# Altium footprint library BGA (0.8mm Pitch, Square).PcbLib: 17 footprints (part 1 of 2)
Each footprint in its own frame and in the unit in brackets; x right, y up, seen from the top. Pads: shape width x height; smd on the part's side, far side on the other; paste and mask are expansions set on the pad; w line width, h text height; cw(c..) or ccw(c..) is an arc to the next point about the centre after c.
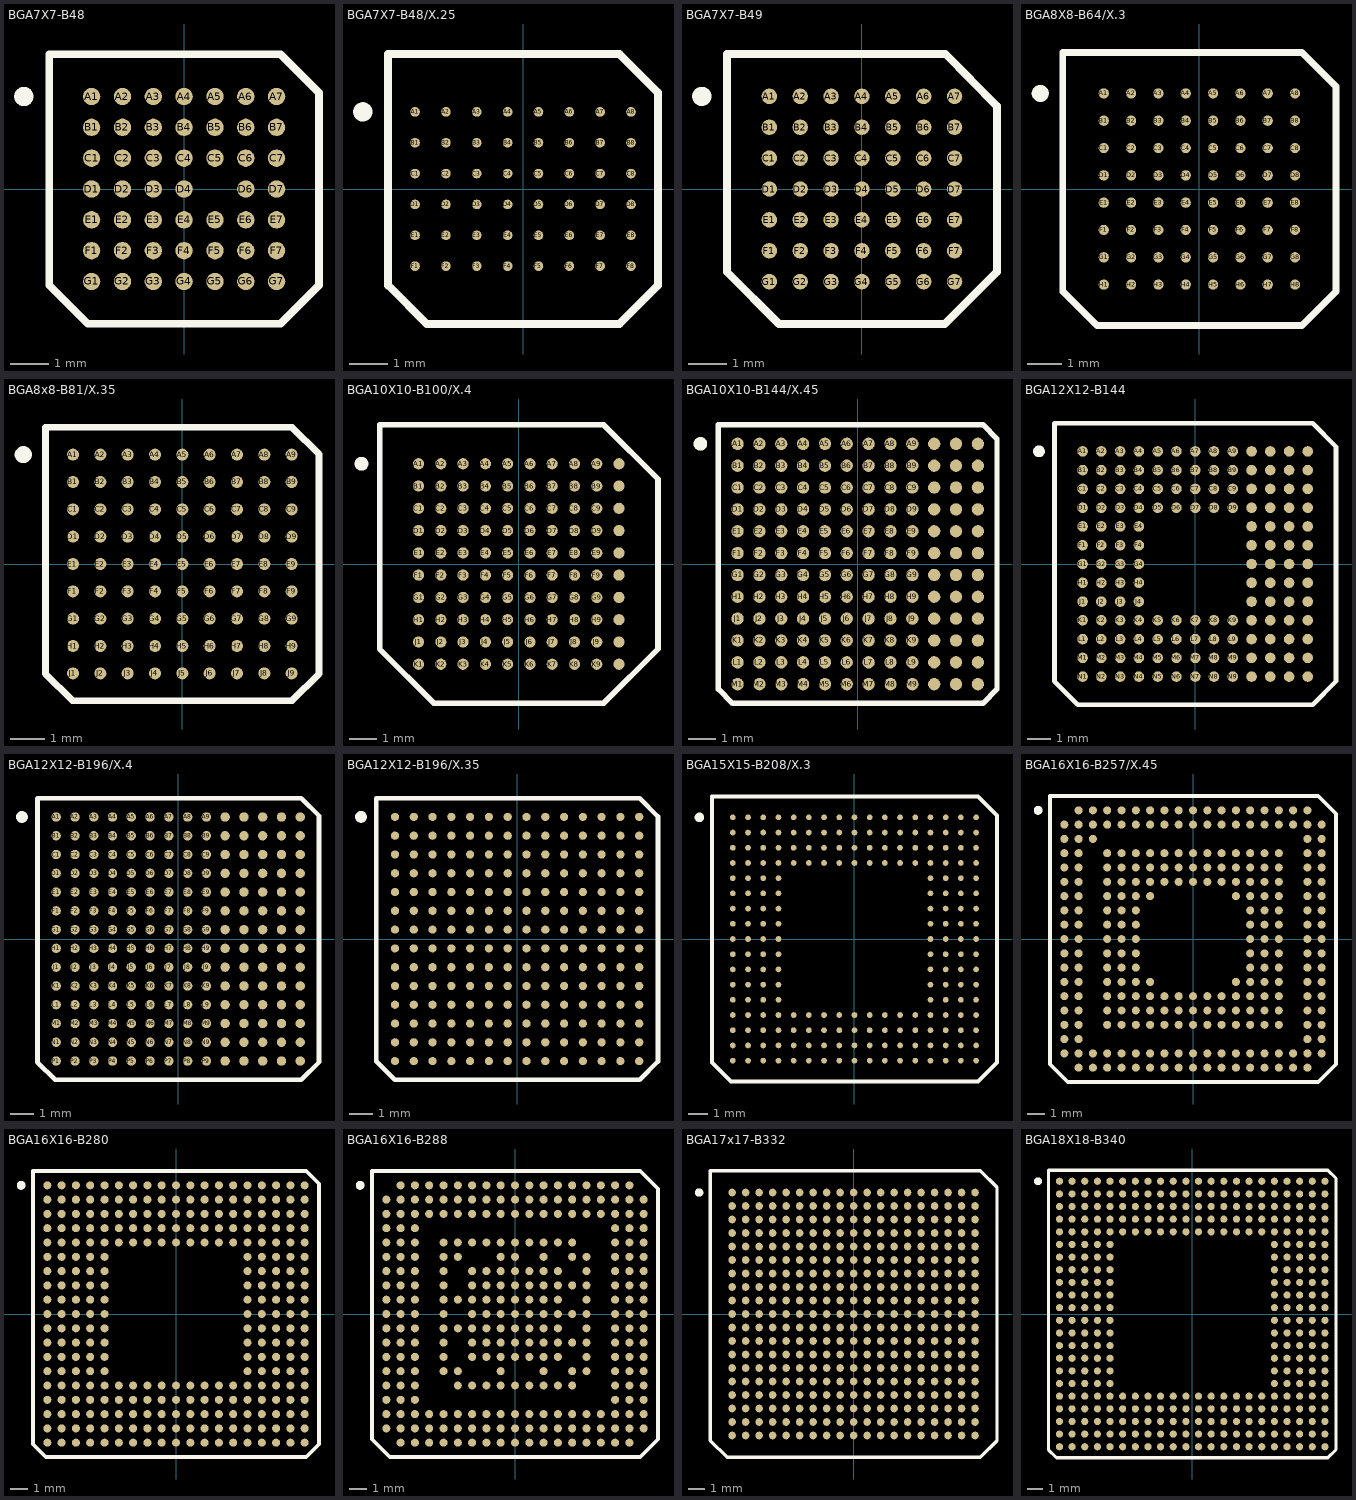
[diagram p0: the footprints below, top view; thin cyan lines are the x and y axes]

## BGA7X7-B48 [mm]
pads (48):
  round 0.45 smd: A1(-2.4,2.4) A2(-1.6,2.4) A3(-0.8,2.4) A4(0,2.4) A5(0.8,2.4) A6(1.6,2.4) A7(2.4,2.4) B1(-2.4,1.6) B2(-1.6,1.6) B3(-0.8,1.6) B4(0,1.6) B5(0.8,1.6) B6(1.6,1.6) B7(2.4,1.6) C1(-2.4,0.8) C2(-1.6,0.8) C3(-0.8,0.8) C4(0,0.8) C5(0.8,0.8) C6(1.6,0.8) C7(2.4,0.8) D1(-2.4,0) D2(-1.6,0) D3(-0.8,0) D4(0,0) D6(1.6,0) D7(2.4,0) E1(-2.4,-0.8) E2(-1.6,-0.8) E3(-0.8,-0.8) E4(0,-0.8) E5(0.8,-0.8) E6(1.6,-0.8) E7(2.4,-0.8) F1(-2.4,-1.6) F2(-1.6,-1.6) F3(-0.8,-1.6) F4(0,-1.6) F5(0.8,-1.6) F6(1.6,-1.6) F7(2.4,-1.6) G1(-2.4,-2.4) G2(-1.6,-2.4) G3(-0.8,-2.4) G4(0,-2.4) G5(0.8,-2.4) G6(1.6,-2.4) G7(2.4,-2.4)
Top Overlay:
  circle w0.25: c-4.16,2.4 r0.125
  lines w0.2: -3.5,-2.5 -3.5,3.5 2.5,3.5 3.5,2.5 3.5,-2.5 2.5,-3.5 -2.5,-3.5 -3.5,-2.5

## BGA7X7-B48/X.25 [mm]
pads (48):
  round 0.25 smd: A1(-2.8,2) A2(-2,2) A3(-1.2,2) A4(-0.4,2) A5(0.4,2) A6(1.2,2) A7(2,2) A8(2.8,2) B1(-2.8,1.2) B2(-2,1.2) B3(-1.2,1.2) B4(-0.4,1.2) B5(0.4,1.2) B6(1.2,1.2) B7(2,1.2) B8(2.8,1.2) C1(-2.8,0.4) C2(-2,0.4) C3(-1.2,0.4) C4(-0.4,0.4) C5(0.4,0.4) C6(1.2,0.4) C7(2,0.4) C8(2.8,0.4) D1(-2.8,-0.4) D2(-2,-0.4) D3(-1.2,-0.4) D4(-0.4,-0.4) D5(0.4,-0.4) D6(1.2,-0.4) D7(2,-0.4) D8(2.8,-0.4) E1(-2.8,-1.2) E2(-2,-1.2) E3(-1.2,-1.2) E4(-0.4,-1.2) E5(0.4,-1.2) E6(1.2,-1.2) E7(2,-1.2) E8(2.8,-1.2) F1(-2.8,-2) F2(-2,-2) F3(-1.2,-2) F4(-0.4,-2) F5(0.4,-2) F6(1.2,-2) F7(2,-2) F8(2.8,-2)
Top Overlay:
  circle w0.25: c-4.155,2 r0.125
  lines w0.2: -3.5,-2.5 -3.5,3.5 2.5,3.5 3.5,2.5 3.5,-2.5 2.5,-3.5 -2.5,-3.5 -3.5,-2.5

## BGA7X7-B49 [mm]
pads (49):
  round 0.4 smd: A1(-2.4,2.4) A2(-1.6,2.4) A3(-0.8,2.4) A4(0,2.4) A5(0.8,2.4) A6(1.6,2.4) A7(2.4,2.4) B1(-2.4,1.6) B2(-1.6,1.6) B3(-0.8,1.6) B4(0,1.6) B5(0.8,1.6) B6(1.6,1.6) B7(2.4,1.6) C1(-2.4,0.8) C2(-1.6,0.8) C3(-0.8,0.8) C4(0,0.8) C5(0.8,0.8) C6(1.6,0.8) C7(2.4,0.8) D1(-2.4,0) D2(-1.6,0) D3(-0.8,0) D4(0,0) D5(0.8,0) D6(1.6,0) D7(2.4,0) E1(-2.4,-0.8) E2(-1.6,-0.8) E3(-0.8,-0.8) E4(0,-0.8) E5(0.8,-0.8) E6(1.6,-0.8) E7(2.4,-0.8) F1(-2.4,-1.6) F2(-1.6,-1.6) F3(-0.8,-1.6) F4(0,-1.6) F5(0.8,-1.6) F6(1.6,-1.6) F7(2.4,-1.6) G1(-2.4,-2.4) G2(-1.6,-2.4) G3(-0.8,-2.4) G4(0,-2.4) G5(0.8,-2.4) G6(1.6,-2.4) G7(2.4,-2.4)
Top Overlay:
  circle w0.25: c-4.15,2.4 r0.125
  lines w0.2: 2.149,3.5 -3.5,3.5 -3.5,-2.149 -2.149,-3.5 2.149,-3.5 3.5,-2.149 3.5,2.149 2.159,3.5

## BGA8X8-B64/X.3 [mm]
pads (64):
  round 0.3 smd: A1(-2.8,2.8) A2(-2,2.8) A3(-1.2,2.8) A4(-0.4,2.8) A5(0.4,2.8) A6(1.2,2.8) A7(2,2.8) A8(2.8,2.8) B1(-2.8,2) B2(-2,2) B3(-1.2,2) B4(-0.4,2) B5(0.4,2) B6(1.2,2) B7(2,2) B8(2.8,2) C1(-2.8,1.2) C2(-2,1.2) C3(-1.2,1.2) C4(-0.4,1.2) C5(0.4,1.2) C6(1.2,1.2) C7(2,1.2) C8(2.8,1.2) D1(-2.8,0.4) D2(-2,0.4) D3(-1.2,0.4) D4(-0.4,0.4) D5(0.4,0.4) D6(1.2,0.4) D7(2,0.4) D8(2.8,0.4) E1(-2.8,-0.4) E2(-2,-0.4) E3(-1.2,-0.4) E4(-0.4,-0.4) E5(0.4,-0.4) E6(1.2,-0.4) E7(2,-0.4) E8(2.8,-0.4) F1(-2.8,-1.2) F2(-2,-1.2) F3(-1.2,-1.2) F4(-0.4,-1.2) F5(0.4,-1.2) F6(1.2,-1.2) F7(2,-1.2) F8(2.8,-1.2) G1(-2.8,-2) G2(-2,-2) G3(-1.2,-2) G4(-0.4,-2) G5(0.4,-2) G6(1.2,-2) G7(2,-2) G8(2.8,-2) H1(-2.8,-2.8) H2(-2,-2.8) H3(-1.2,-2.8) H4(-0.4,-2.8) H5(0.4,-2.8) H6(1.2,-2.8) H7(2,-2.8) H8(2.8,-2.8)
Top Overlay:
  circle w0.25: c-4.66,2.8 r0.125
  lines w0.2: -4,-3 -3,-4 3,-4 4,-3 4,3 3,4 -4,4 -4,-3

## BGA8x8-B81/X.35 [mm]
pads (81):
  round 0.35 smd: A1(-3.2,3.2) A2(-2.4,3.2) A3(-1.6,3.2) A4(-0.8,3.2) A5(0,3.2) A6(0.8,3.2) A7(1.6,3.2) A8(2.4,3.2) A9(3.2,3.2) B1(-3.2,2.4) B2(-2.4,2.4) B3(-1.6,2.4) B4(-0.8,2.4) B5(0,2.4) B6(0.8,2.4) B7(1.6,2.4) B8(2.4,2.4) B9(3.2,2.4) C1(-3.2,1.6) C2(-2.4,1.6) C3(-1.6,1.6) C4(-0.8,1.6) C5(0,1.6) C6(0.8,1.6) C7(1.6,1.6) C8(2.4,1.6) C9(3.2,1.6) D1(-3.2,0.8) D2(-2.4,0.8) D3(-1.6,0.8) D4(-0.8,0.8) D5(0,0.8) D6(0.8,0.8) D7(1.6,0.8) D8(2.4,0.8) D9(3.2,0.8) E1(-3.2,0) E2(-2.4,0) E3(-1.6,0) E4(-0.8,0) E5(0,0) E6(0.8,0) E7(1.6,0) E8(2.4,0) E9(3.2,0) F1(-3.2,-0.8) F2(-2.4,-0.8) F3(-1.6,-0.8) F4(-0.8,-0.8) F5(0,-0.8) F6(0.8,-0.8) F7(1.6,-0.8) F8(2.4,-0.8) F9(3.2,-0.8) G1(-3.2,-1.6) G2(-2.4,-1.6) G3(-1.6,-1.6) G4(-0.8,-1.6) G5(0,-1.6) G6(0.8,-1.6) G7(1.6,-1.6) G8(2.4,-1.6) G9(3.2,-1.6) H1(-3.2,-2.4) H2(-2.4,-2.4) H3(-1.6,-2.4) H4(-0.8,-2.4) H5(0,-2.4) H6(0.8,-2.4) H7(1.6,-2.4) H8(2.4,-2.4) H9(3.2,-2.4) J1(-3.2,-3.2) J2(-2.4,-3.2) J3(-1.6,-3.2) J4(-0.8,-3.2) J5(0,-3.2) J6(0.8,-3.2) J7(1.6,-3.2) J8(2.4,-3.2) J9(3.2,-3.2)
Top Overlay:
  circle w0.25: c-4.655,3.2 r0.125
  lines w0.2: -4,-3.213 -4,4 3.213,4 4,3.213 4,-3.213 3.213,-4 -3.213,-4 -4,-3.213

## BGA10X10-B100/X.4 [mm]
pads (100):
  round 0.4 smd: A1(-3.6,3.6) A2(-2.8,3.6) A3(-2,3.6) A4(-1.2,3.6) A5(-0.4,3.6) A6(0.4,3.6) A7(1.2,3.6) A8(2,3.6) A9(2.8,3.6) A10(3.6,3.6) B1(-3.6,2.8) B2(-2.8,2.8) B3(-2,2.8) B4(-1.2,2.8) B5(-0.4,2.8) B6(0.4,2.8) B7(1.2,2.8) B8(2,2.8) B9(2.8,2.8) B10(3.6,2.8) C1(-3.6,2) C2(-2.8,2) C3(-2,2) C4(-1.2,2) C5(-0.4,2) C6(0.4,2) C7(1.2,2) C8(2,2) C9(2.8,2) C10(3.6,2) D1(-3.6,1.2) D2(-2.8,1.2) D3(-2,1.2) D4(-1.2,1.2) D5(-0.4,1.2) D6(0.4,1.2) D7(1.2,1.2) D8(2,1.2) D9(2.8,1.2) D10(3.6,1.2) E1(-3.6,0.4) E2(-2.8,0.4) E3(-2,0.4) E4(-1.2,0.4) E5(-0.4,0.4) E6(0.4,0.4) E7(1.2,0.4) E8(2,0.4) E9(2.8,0.4) E10(3.6,0.4) F1(-3.6,-0.4) F2(-2.8,-0.4) F3(-2,-0.4) F4(-1.2,-0.4) F5(-0.4,-0.4) F6(0.4,-0.4) F7(1.2,-0.4) F8(2,-0.4) F9(2.8,-0.4) F10(3.6,-0.4) G1(-3.6,-1.2) G2(-2.8,-1.2) G3(-2,-1.2) G4(-1.2,-1.2) G5(-0.4,-1.2) G6(0.4,-1.2) G7(1.2,-1.2) G8(2,-1.2) G9(2.8,-1.2) G10(3.6,-1.2) H1(-3.6,-2) H2(-2.8,-2) H3(-2,-2) H4(-1.2,-2) H5(-0.4,-2) H6(0.4,-2) H7(1.2,-2) H8(2,-2) H9(2.8,-2) H10(3.6,-2) J1(-3.6,-2.8) J2(-2.8,-2.8) J3(-2,-2.8) J4(-1.2,-2.8) J5(-0.4,-2.8) J6(0.4,-2.8) J7(1.2,-2.8) J8(2,-2.8) J9(2.8,-2.8) J10(3.6,-2.8) K1(-3.6,-3.6) K2(-2.8,-3.6) K3(-2,-3.6) K4(-1.2,-3.6) K5(-0.4,-3.6) K6(0.4,-3.6) K7(1.2,-3.6) K8(2,-3.6) K9(2.8,-3.6) K10(3.6,-3.6)
Top Overlay:
  circle w0.25: c-5.65,3.6 r0.125
  lines w0.2: -5,-3.049 -5,5 3.049,5 5,3.049 5,-3.049 3.049,-5 -3.049,-5 -5,-3.049

## BGA10X10-B144/X.45 [mm]
pads (144):
  round 0.45 smd: A1(-4.4,4.4) A2(-3.6,4.4) A3(-2.8,4.4) A4(-2,4.4) A5(-1.2,4.4) A6(-0.4,4.4) A7(0.4,4.4) A8(1.2,4.4) A9(2,4.4) A10(2.8,4.4) A11(3.6,4.4) A12(4.4,4.4) B1(-4.4,3.6) B2(-3.6,3.6) B3(-2.8,3.6) B4(-2,3.6) B5(-1.2,3.6) B6(-0.4,3.6) B7(0.4,3.6) B8(1.2,3.6) B9(2,3.6) B10(2.8,3.6) B11(3.6,3.6) B12(4.4,3.6) C1(-4.4,2.8) C2(-3.6,2.8) C3(-2.8,2.8) C4(-2,2.8) C5(-1.2,2.8) C6(-0.4,2.8) C7(0.4,2.8) C8(1.2,2.8) C9(2,2.8) C10(2.8,2.8) C11(3.6,2.8) C12(4.4,2.8) D1(-4.4,2) D2(-3.6,2) D3(-2.8,2) D4(-2,2) D5(-1.2,2) D6(-0.4,2) D7(0.4,2) D8(1.2,2) D9(2,2) D10(2.8,2) D11(3.6,2) D12(4.4,2) E1(-4.4,1.2) E2(-3.6,1.2) E3(-2.8,1.2) E4(-2,1.2) E5(-1.2,1.2) E6(-0.4,1.2) E7(0.4,1.2) E8(1.2,1.2) E9(2,1.2) E10(2.8,1.2) E11(3.6,1.2) E12(4.4,1.2) F1(-4.4,0.4) F2(-3.6,0.4) F3(-2.8,0.4) F4(-2,0.4) F5(-1.2,0.4) F6(-0.4,0.4) F7(0.4,0.4) F8(1.2,0.4) F9(2,0.4) F10(2.8,0.4) F11(3.6,0.4) F12(4.4,0.4) G1(-4.4,-0.4) G2(-3.6,-0.4) G3(-2.8,-0.4) G4(-2,-0.4) G5(-1.2,-0.4) G6(-0.4,-0.4) G7(0.4,-0.4) G8(1.2,-0.4) G9(2,-0.4) G10(2.8,-0.4) G11(3.6,-0.4) G12(4.4,-0.4) H1(-4.4,-1.2) H2(-3.6,-1.2) H3(-2.8,-1.2) H4(-2,-1.2) H5(-1.2,-1.2) H6(-0.4,-1.2) H7(0.4,-1.2) H8(1.2,-1.2) H9(2,-1.2) H10(2.8,-1.2) H11(3.6,-1.2) H12(4.4,-1.2) J1(-4.4,-2) J2(-3.6,-2) J3(-2.8,-2) J4(-2,-2) J5(-1.2,-2) J6(-0.4,-2) J7(0.4,-2) J8(1.2,-2) J9(2,-2) J10(2.8,-2) J11(3.6,-2) J12(4.4,-2) K1(-4.4,-2.8) K2(-3.6,-2.8) K3(-2.8,-2.8) K4(-2,-2.8) K5(-1.2,-2.8) K6(-0.4,-2.8) K7(0.4,-2.8) K8(1.2,-2.8) K9(2,-2.8) K10(2.8,-2.8) K11(3.6,-2.8) K12(4.4,-2.8) L1(-4.4,-3.6) L2(-3.6,-3.6) L3(-2.8,-3.6) L4(-2,-3.6) L5(-1.2,-3.6) L6(-0.4,-3.6) L7(0.4,-3.6) L8(1.2,-3.6) L9(2,-3.6) L10(2.8,-3.6) L11(3.6,-3.6) L12(4.4,-3.6) M1(-4.4,-4.4) M2(-3.6,-4.4) M3(-2.8,-4.4) M4(-2,-4.4) M5(-1.2,-4.4) M6(-0.4,-4.4) M7(0.4,-4.4) M8(1.2,-4.4) M9(2,-4.4) M10(2.8,-4.4) M11(3.6,-4.4) M12(4.4,-4.4)
Top Overlay:
  circle w0.25: c-5.76,4.4 r0.125
  lines w0.2: -5.1,-4.584 -5.1,5.1 4.584,5.1 5.1,4.584 5.1,-4.584 4.584,-5.1 -4.584,-5.1 -5.1,-4.584

## BGA12X12-B144 [mm]
pads (144):
  round 0.45 smd: A1(-4.8,4.8) A2(-4,4.8) A3(-3.2,4.8) A4(-2.4,4.8) A5(-1.6,4.8) A6(-0.8,4.8) A7(0,4.8) A8(0.8,4.8) A9(1.6,4.8) A10(2.4,4.8) A11(3.2,4.8) A12(4,4.8) A13(4.8,4.8) B1(-4.8,4) B2(-4,4) B3(-3.2,4) B4(-2.4,4) B5(-1.6,4) B6(-0.8,4) B7(0,4) B8(0.8,4) B9(1.6,4) B10(2.4,4) B11(3.2,4) B12(4,4) B13(4.8,4) C1(-4.8,3.2) C2(-4,3.2) C3(-3.2,3.2) C4(-2.4,3.2) C5(-1.6,3.2) C6(-0.8,3.2) C7(0,3.2) C8(0.8,3.2) C9(1.6,3.2) C10(2.4,3.2) C11(3.2,3.2) C12(4,3.2) C13(4.8,3.2) D1(-4.8,2.4) D2(-4,2.4) D3(-3.2,2.4) D4(-2.4,2.4) D5(-1.6,2.4) D6(-0.8,2.4) D7(0,2.4) D8(0.8,2.4) D9(1.6,2.4) D10(2.4,2.4) D11(3.2,2.4) D12(4,2.4) D13(4.8,2.4) E1(-4.8,1.6) E2(-4,1.6) E3(-3.2,1.6) E4(-2.4,1.6) E10(2.4,1.6) E11(3.2,1.6) E12(4,1.6) E13(4.8,1.6) F1(-4.8,0.8) F2(-4,0.8) F3(-3.2,0.8) F4(-2.4,0.8) F10(2.4,0.8) F11(3.2,0.8) F12(4,0.8) F13(4.8,0.8) G1(-4.8,0) G2(-4,0) G3(-3.2,0) G4(-2.4,0) G10(2.4,0) G11(3.2,0) G12(4,0) G13(4.8,0) H1(-4.8,-0.8) H2(-4,-0.8) H3(-3.2,-0.8) H4(-2.4,-0.8) H10(2.4,-0.8) H11(3.2,-0.8) H12(4,-0.8) H13(4.8,-0.8) J1(-4.8,-1.6) J2(-4,-1.6) J3(-3.2,-1.6) J4(-2.4,-1.6) J10(2.4,-1.6) J11(3.2,-1.6) J12(4,-1.6) J13(4.8,-1.6) K1(-4.8,-2.4) K2(-4,-2.4) K3(-3.2,-2.4) K4(-2.4,-2.4) K5(-1.6,-2.4) K6(-0.8,-2.4) K7(0,-2.4) K8(0.8,-2.4) K9(1.6,-2.4) K10(2.4,-2.4) K11(3.2,-2.4) K12(4,-2.4) K13(4.8,-2.4) L1(-4.8,-3.2) L2(-4,-3.2) L3(-3.2,-3.2) L4(-2.4,-3.2) L5(-1.6,-3.2) L6(-0.8,-3.2) L7(0,-3.2) L8(0.8,-3.2) L9(1.6,-3.2) L10(2.4,-3.2) L11(3.2,-3.2) L12(4,-3.2) L13(4.8,-3.2) M1(-4.8,-4) M2(-4,-4) M3(-3.2,-4) M4(-2.4,-4) M5(-1.6,-4) M6(-0.8,-4) M7(0,-4) M8(0.8,-4) M9(1.6,-4) M10(2.4,-4) M11(3.2,-4) M12(4,-4) M13(4.8,-4) N1(-4.8,-4.8) N2(-4,-4.8) N3(-3.2,-4.8) N4(-2.4,-4.8) N5(-1.6,-4.8) N6(-0.8,-4.8) N7(0,-4.8) N8(0.8,-4.8) N9(1.6,-4.8) N10(2.4,-4.8) N11(3.2,-4.8) N12(4,-4.8) N13(4.8,-4.8)
Top Overlay:
  circle w0.25: c-6.66,4.8 r0.125
  lines w0.2: -6,-5 -6,6 5,6 6,5 6,-5 5,-6 -5,-6 -6,-5

## BGA12X12-B196/X.4 [mm]
pads (196):
  round 0.4 smd: A1(-5.2,5.2) A2(-4.4,5.2) A3(-3.6,5.2) A4(-2.8,5.2) A5(-2,5.2) A6(-1.2,5.2) A7(-0.4,5.2) A8(0.4,5.2) A9(1.2,5.2) A10(2,5.2) A11(2.8,5.2) A12(3.6,5.2) A13(4.4,5.2) A14(5.2,5.2) B1(-5.2,4.4) B2(-4.4,4.4) B3(-3.6,4.4) B4(-2.8,4.4) B5(-2,4.4) B6(-1.2,4.4) B7(-0.4,4.4) B8(0.4,4.4) B9(1.2,4.4) B10(2,4.4) B11(2.8,4.4) B12(3.6,4.4) B13(4.4,4.4) B14(5.2,4.4) C1(-5.2,3.6) C2(-4.4,3.6) C3(-3.6,3.6) C4(-2.8,3.6) C5(-2,3.6) C6(-1.2,3.6) C7(-0.4,3.6) C8(0.4,3.6) C9(1.2,3.6) C10(2,3.6) C11(2.8,3.6) C12(3.6,3.6) C13(4.4,3.6) C14(5.2,3.6) D1(-5.2,2.8) D2(-4.4,2.8) D3(-3.6,2.8) D4(-2.8,2.8) D5(-2,2.8) D6(-1.2,2.8) D7(-0.4,2.8) D8(0.4,2.8) D9(1.2,2.8) D10(2,2.8) D11(2.8,2.8) D12(3.6,2.8) D13(4.4,2.8) D14(5.2,2.8) E1(-5.2,2) E2(-4.4,2) E3(-3.6,2) E4(-2.8,2) E5(-2,2) E6(-1.2,2) E7(-0.4,2) E8(0.4,2) E9(1.2,2) E10(2,2) E11(2.8,2) E12(3.6,2) E13(4.4,2) E14(5.2,2) F1(-5.2,1.2) F2(-4.4,1.2) F3(-3.6,1.2) F4(-2.8,1.2) F5(-2,1.2) F6(-1.2,1.2) F7(-0.4,1.2) F8(0.4,1.2) F9(1.2,1.2) F10(2,1.2) F11(2.8,1.2) F12(3.6,1.2) F13(4.4,1.2) F14(5.2,1.2) G1(-5.2,0.4) G2(-4.4,0.4) G3(-3.6,0.4) G4(-2.8,0.4) G5(-2,0.4) G6(-1.2,0.4) G7(-0.4,0.4) G8(0.4,0.4) G9(1.2,0.4) G10(2,0.4) G11(2.8,0.4) G12(3.6,0.4) G13(4.4,0.4) G14(5.2,0.4) H1(-5.2,-0.4) H2(-4.4,-0.4) H3(-3.6,-0.4) H4(-2.8,-0.4) H5(-2,-0.4) H6(-1.2,-0.4) H7(-0.4,-0.4) H8(0.4,-0.4) H9(1.2,-0.4) H10(2,-0.4) H11(2.8,-0.4) H12(3.6,-0.4) H13(4.4,-0.4) H14(5.2,-0.4) J1(-5.2,-1.2) J2(-4.4,-1.2) J3(-3.6,-1.2) J4(-2.8,-1.2) J5(-2,-1.2) J6(-1.2,-1.2) J7(-0.4,-1.2) J8(0.4,-1.2) J9(1.2,-1.2) J10(2,-1.2) J11(2.8,-1.2) J12(3.6,-1.2) J13(4.4,-1.2) J14(5.2,-1.2) K1(-5.2,-2) K2(-4.4,-2) K3(-3.6,-2) K4(-2.8,-2) K5(-2,-2) K6(-1.2,-2) K7(-0.4,-2) K8(0.4,-2) K9(1.2,-2) K10(2,-2) K11(2.8,-2) K12(3.6,-2) K13(4.4,-2) K14(5.2,-2) L1(-5.2,-2.8) L2(-4.4,-2.8) L3(-3.6,-2.8) L4(-2.8,-2.8) L5(-2,-2.8) L6(-1.2,-2.8) L7(-0.4,-2.8) L8(0.4,-2.8) L9(1.2,-2.8) L10(2,-2.8) L11(2.8,-2.8) L12(3.6,-2.8) L13(4.4,-2.8) L14(5.2,-2.8) M1(-5.2,-3.6) M2(-4.4,-3.6) M3(-3.6,-3.6) M4(-2.8,-3.6) M5(-2,-3.6) M6(-1.2,-3.6) M7(-0.4,-3.6) M8(0.4,-3.6) M9(1.2,-3.6) M10(2,-3.6) M11(2.8,-3.6) M12(3.6,-3.6) M13(4.4,-3.6) M14(5.2,-3.6) N1(-5.2,-4.4) N2(-4.4,-4.4) N3(-3.6,-4.4) N4(-2.8,-4.4) N5(-2,-4.4) N6(-1.2,-4.4) N7(-0.4,-4.4) N8(0.4,-4.4) N9(1.2,-4.4) N10(2,-4.4) N11(2.8,-4.4) N12(3.6,-4.4) N13(4.4,-4.4) N14(5.2,-4.4) P1(-5.2,-5.2) P2(-4.4,-5.2) P3(-3.6,-5.2) P4(-2.8,-5.2) P5(-2,-5.2) P6(-1.2,-5.2) P7(-0.4,-5.2) P8(0.4,-5.2) P9(1.2,-5.2) P10(2,-5.2) P11(2.8,-5.2) P12(3.6,-5.2) P13(4.4,-5.2) P14(5.2,-5.2)
Top Overlay:
  circle w0.25: c-6.66,5.2 r0.125
  lines w0.2: 5.249,-6 6,-5.249 6,5.249 ; 5.249,-6 5.249,-6 ; 5.249,-6 -5.249,-6 -6,-5.249 -6,6 5.249,6 6,5.249 ; 6,5.249 6,5.249

## BGA12X12-B196/X.35 [mm]
pads (196):
  round 0.35 smd: A1(-5.2,5.2) A2(-4.4,5.2) A3(-3.6,5.2) A4(-2.8,5.2) A5(-2,5.2) A6(-1.2,5.2) A7(-0.4,5.2) A8(0.4,5.2) A9(1.2,5.2) A10(2,5.2) A11(2.8,5.2) A12(3.6,5.2) A13(4.4,5.2) A14(5.2,5.2) B1(-5.2,4.4) B2(-4.4,4.4) B3(-3.6,4.4) B4(-2.8,4.4) B5(-2,4.4) B6(-1.2,4.4) B7(-0.4,4.4) B8(0.4,4.4) B9(1.2,4.4) B10(2,4.4) B11(2.8,4.4) B12(3.6,4.4) B13(4.4,4.4) B14(5.2,4.4) C1(-5.2,3.6) C2(-4.4,3.6) C3(-3.6,3.6) C4(-2.8,3.6) C5(-2,3.6) C6(-1.2,3.6) C7(-0.4,3.6) C8(0.4,3.6) C9(1.2,3.6) C10(2,3.6) C11(2.8,3.6) C12(3.6,3.6) C13(4.4,3.6) C14(5.2,3.6) D1(-5.2,2.8) D2(-4.4,2.8) D3(-3.6,2.8) D4(-2.8,2.8) D5(-2,2.8) D6(-1.2,2.8) D7(-0.4,2.8) D8(0.4,2.8) D9(1.2,2.8) D10(2,2.8) D11(2.8,2.8) D12(3.6,2.8) D13(4.4,2.8) D14(5.2,2.8) E1(-5.2,2) E2(-4.4,2) E3(-3.6,2) E4(-2.8,2) E5(-2,2) E6(-1.2,2) E7(-0.4,2) E8(0.4,2) E9(1.2,2) E10(2,2) E11(2.8,2) E12(3.6,2) E13(4.4,2) E14(5.2,2) F1(-5.2,1.2) F2(-4.4,1.2) F3(-3.6,1.2) F4(-2.8,1.2) F5(-2,1.2) F6(-1.2,1.2) F7(-0.4,1.2) F8(0.4,1.2) F9(1.2,1.2) F10(2,1.2) F11(2.8,1.2) F12(3.6,1.2) F13(4.4,1.2) F14(5.2,1.2) G1(-5.2,0.4) G2(-4.4,0.4) G3(-3.6,0.4) G4(-2.8,0.4) G5(-2,0.4) G6(-1.2,0.4) G7(-0.4,0.4) G8(0.4,0.4) G9(1.2,0.4) G10(2,0.4) G11(2.8,0.4) G12(3.6,0.4) G13(4.4,0.4) G14(5.2,0.4) H1(-5.2,-0.4) H2(-4.4,-0.4) H3(-3.6,-0.4) H4(-2.8,-0.4) H5(-2,-0.4) H6(-1.2,-0.4) H7(-0.4,-0.4) H8(0.4,-0.4) H9(1.2,-0.4) H10(2,-0.4) H11(2.8,-0.4) H12(3.6,-0.4) H13(4.4,-0.4) H14(5.2,-0.4) J1(-5.2,-1.2) J2(-4.4,-1.2) J3(-3.6,-1.2) J4(-2.8,-1.2) J5(-2,-1.2) J6(-1.2,-1.2) J7(-0.4,-1.2) J8(0.4,-1.2) J9(1.2,-1.2) J10(2,-1.2) J11(2.8,-1.2) J12(3.6,-1.2) J13(4.4,-1.2) J14(5.2,-1.2) K1(-5.2,-2) K2(-4.4,-2) K3(-3.6,-2) K4(-2.8,-2) K5(-2,-2) K6(-1.2,-2) K7(-0.4,-2) K8(0.4,-2) K9(1.2,-2) K10(2,-2) K11(2.8,-2) K12(3.6,-2) K13(4.4,-2) K14(5.2,-2) L1(-5.2,-2.8) L2(-4.4,-2.8) L3(-3.6,-2.8) L4(-2.8,-2.8) L5(-2,-2.8) L6(-1.2,-2.8) L7(-0.4,-2.8) L8(0.4,-2.8) L9(1.2,-2.8) L10(2,-2.8) L11(2.8,-2.8) L12(3.6,-2.8) L13(4.4,-2.8) L14(5.2,-2.8) M1(-5.2,-3.6) M2(-4.4,-3.6) M3(-3.6,-3.6) M4(-2.8,-3.6) M5(-2,-3.6) M6(-1.2,-3.6) M7(-0.4,-3.6) M8(0.4,-3.6) M9(1.2,-3.6) M10(2,-3.6) M11(2.8,-3.6) M12(3.6,-3.6) M13(4.4,-3.6) M14(5.2,-3.6) N1(-5.2,-4.4) N2(-4.4,-4.4) N3(-3.6,-4.4) N4(-2.8,-4.4) N5(-2,-4.4) N6(-1.2,-4.4) N7(-0.4,-4.4) N8(0.4,-4.4) N9(1.2,-4.4) N10(2,-4.4) N11(2.8,-4.4) N12(3.6,-4.4) N13(4.4,-4.4) N14(5.2,-4.4) P1(-5.2,-5.2) P2(-4.4,-5.2) P3(-3.6,-5.2) P4(-2.8,-5.2) P5(-2,-5.2) P6(-1.2,-5.2) P7(-0.4,-5.2) P8(0.4,-5.2) P9(1.2,-5.2) P10(2,-5.2) P11(2.8,-5.2) P12(3.6,-5.2) P13(4.4,-5.2) P14(5.2,-5.2)
Top Overlay:
  circle w0.25: c-6.65,5.2 r0.125
  lines w0.2: -6,-5.213 -6,6 5.213,6 6,5.213 6,-5.213 5.213,-6 -5.213,-6 -6,-5.213

## BGA15X15-B208/X.3 [mm]
pads (208):
  round 0.3 smd: A1(-6.4,6.4) A2(-5.6,6.4) A3(-4.8,6.4) A4(-4,6.4) A5(-3.2,6.4) A6(-2.4,6.4) A7(-1.6,6.4) A8(-0.8,6.4) A9(0,6.4) A10(0.8,6.4) A11(1.6,6.4) A12(2.4,6.4) A13(3.2,6.4) A14(4,6.4) A15(4.8,6.4) A16(5.6,6.4) A17(6.4,6.4) B1(-6.4,5.6) B2(-5.6,5.6) B3(-4.8,5.6) B4(-4,5.6) B5(-3.2,5.6) B6(-2.4,5.6) B7(-1.6,5.6) B8(-0.8,5.6) B9(0,5.6) B10(0.8,5.6) B11(1.6,5.6) B12(2.4,5.6) B13(3.2,5.6) B14(4,5.6) B15(4.8,5.6) B16(5.6,5.6) B17(6.4,5.6) C1(-6.4,4.8) C2(-5.6,4.8) C3(-4.8,4.8) C4(-4,4.8) C5(-3.2,4.8) C6(-2.4,4.8) C7(-1.6,4.8) C8(-0.8,4.8) C9(0,4.8) C10(0.8,4.8) C11(1.6,4.8) C12(2.4,4.8) C13(3.2,4.8) C14(4,4.8) C15(4.8,4.8) C16(5.6,4.8) C17(6.4,4.8) D1(-6.4,4) D2(-5.6,4) D3(-4.8,4) D4(-4,4) D5(-3.2,4) D6(-2.4,4) D7(-1.6,4) D8(-0.8,4) D9(0,4) D10(0.8,4) D11(1.6,4) D12(2.4,4) D13(3.2,4) D14(4,4) D15(4.8,4) D16(5.6,4) D17(6.4,4) E1(-6.4,3.2) E2(-5.6,3.2) E3(-4.8,3.2) E4(-4,3.2) E14(4,3.2) E15(4.8,3.2) E16(5.6,3.2) E17(6.4,3.2) F1(-6.4,2.4) F2(-5.6,2.4) F3(-4.8,2.4) F4(-4,2.4) F14(4,2.4) F15(4.8,2.4) F16(5.6,2.4) F17(6.4,2.4) G1(-6.4,1.6) G2(-5.6,1.6) G3(-4.8,1.6) G4(-4,1.6) G14(4,1.6) G15(4.8,1.6) G16(5.6,1.6) G17(6.4,1.6) H1(-6.4,0.8) H2(-5.6,0.8) H3(-4.8,0.8) H4(-4,0.8) H14(4,0.8) H15(4.8,0.8) H16(5.6,0.8) H17(6.4,0.8) J1(-6.4,0) J2(-5.6,0) J3(-4.8,0) J4(-4,0) J14(4,0) J15(4.8,0) J16(5.6,0) J17(6.4,0) K1(-6.4,-0.8) K2(-5.6,-0.8) K3(-4.8,-0.8) K4(-4,-0.8) K14(4,-0.8) K15(4.8,-0.8) K16(5.6,-0.8) K17(6.4,-0.8) L1(-6.4,-1.6) L2(-5.6,-1.6) L3(-4.8,-1.6) L4(-4,-1.6) L14(4,-1.6) L15(4.8,-1.6) L16(5.6,-1.6) L17(6.4,-1.6) M1(-6.4,-2.4) M2(-5.6,-2.4) M3(-4.8,-2.4) M4(-4,-2.4) M14(4,-2.4) M15(4.8,-2.4) M16(5.6,-2.4) M17(6.4,-2.4) N1(-6.4,-3.2) N2(-5.6,-3.2) N3(-4.8,-3.2) N4(-4,-3.2) N14(4,-3.2) N15(4.8,-3.2) N16(5.6,-3.2) N17(6.4,-3.2) P1(-6.4,-4) P2(-5.6,-4) P3(-4.8,-4) P4(-4,-4) P5(-3.2,-4) P6(-2.4,-4) P7(-1.6,-4) P8(-0.8,-4) P9(0,-4) P10(0.8,-4) P11(1.6,-4) P12(2.4,-4) P13(3.2,-4) P14(4,-4) P15(4.8,-4) P16(5.6,-4) P17(6.4,-4) R1(-6.4,-4.8) R2(-5.6,-4.8) R3(-4.8,-4.8) R4(-4,-4.8) R5(-3.2,-4.8) R6(-2.4,-4.8) R7(-1.6,-4.8) R8(-0.8,-4.8) R9(0,-4.8) R10(0.8,-4.8) R11(1.6,-4.8) R12(2.4,-4.8) R13(3.2,-4.8) R14(4,-4.8) R15(4.8,-4.8) R16(5.6,-4.8) R17(6.4,-4.8) T1(-6.4,-5.6) T2(-5.6,-5.6) T3(-4.8,-5.6) T4(-4,-5.6) T5(-3.2,-5.6) T6(-2.4,-5.6) T7(-1.6,-5.6) T8(-0.8,-5.6) T9(0,-5.6) T10(0.8,-5.6) T11(1.6,-5.6) T12(2.4,-5.6) T13(3.2,-5.6) T14(4,-5.6) T15(4.8,-5.6) T16(5.6,-5.6) T17(6.4,-5.6) U1(-6.4,-6.4) U2(-5.6,-6.4) U3(-4.8,-6.4) U4(-4,-6.4) U5(-3.2,-6.4) U6(-2.4,-6.4) U7(-1.6,-6.4) U8(-0.8,-6.4) U9(0,-6.4) U10(0.8,-6.4) U11(1.6,-6.4) U12(2.4,-6.4) U13(3.2,-6.4) U14(4,-6.4) U15(4.8,-6.4) U16(5.6,-6.4) U17(6.4,-6.4)
Top Overlay:
  circle w0.25: c-8.16,6.4 r0.125
  lines w0.2: -7.5,-6.5 -6.5,-7.5 6.5,-7.5 7.5,-6.5 7.5,6.5 6.5,7.5 -7.5,7.5 -7.5,-6.5

## BGA16X16-B257/X.45 [mm]
pads (257):
  round 0.45 smd: A2(-6.4,7.2) A3(-5.6,7.2) A4(-4.8,7.2) A5(-4,7.2) A6(-3.2,7.2) A7(-2.4,7.2) A8(-1.6,7.2) A9(-0.8,7.2) A10(0,7.2) A11(0.8,7.2) A12(1.6,7.2) A13(2.4,7.2) A14(3.2,7.2) A15(4,7.2) A16(4.8,7.2) A17(5.6,7.2) A18(6.4,7.2) B1(-7.2,6.4) B2(-6.4,6.4) B3(-5.6,6.4) B4(-4.8,6.4) B5(-4,6.4) B6(-3.2,6.4) B7(-2.4,6.4) B8(-1.6,6.4) B9(-0.8,6.4) B10(0,6.4) B11(0.8,6.4) B12(1.6,6.4) B13(2.4,6.4) B14(3.2,6.4) B15(4,6.4) B16(4.8,6.4) B17(5.6,6.4) B18(6.4,6.4) B19(7.2,6.4) C1(-7.2,5.6) C2(-6.4,5.6) C3(-5.6,5.6) C18(6.4,5.6) C19(7.2,5.6) D1(-7.2,4.8) D2(-6.4,4.8) D4(-4.8,4.8) D5(-4,4.8) D6(-3.2,4.8) D7(-2.4,4.8) D8(-1.6,4.8) D9(-0.8,4.8) D10(0,4.8) D11(0.8,4.8) D12(1.6,4.8) D13(2.4,4.8) D14(3.2,4.8) D15(4,4.8) D16(4.8,4.8) D18(6.4,4.8) D19(7.2,4.8) E1(-7.2,4) E2(-6.4,4) E4(-4.8,4) E5(-4,4) E6(-3.2,4) E7(-2.4,4) E8(-1.6,4) E9(-0.8,4) E10(0,4) E11(0.8,4) E12(1.6,4) E13(2.4,4) E14(3.2,4) E15(4,4) E16(4.8,4) E18(6.4,4) E19(7.2,4) F1(-7.2,3.2) F2(-6.4,3.2) F4(-4.8,3.2) F5(-4,3.2) F6(-3.2,3.2) F7(-2.4,3.2) F8(-1.6,3.2) F9(-0.8,3.2) F10(0,3.2) F11(0.8,3.2) F12(1.6,3.2) F13(2.4,3.2) F14(3.2,3.2) F15(4,3.2) F16(4.8,3.2) F18(6.4,3.2) F19(7.2,3.2) G1(-7.2,2.4) G2(-6.4,2.4) G4(-4.8,2.4) G5(-4,2.4) G6(-3.2,2.4) G7(-2.4,2.4) G13(2.4,2.4) G14(3.2,2.4) G15(4,2.4) G16(4.8,2.4) G18(6.4,2.4) G19(7.2,2.4) H1(-7.2,1.6) H2(-6.4,1.6) H4(-4.8,1.6) H5(-4,1.6) H6(-3.2,1.6) H14(3.2,1.6) H15(4,1.6) H16(4.8,1.6) H18(6.4,1.6) H19(7.2,1.6) J1(-7.2,0.8) J2(-6.4,0.8) J4(-4.8,0.8) J5(-4,0.8) J6(-3.2,0.8) J14(3.2,0.8) J15(4,0.8) J16(4.8,0.8) J18(6.4,0.8) J19(7.2,0.8) K1(-7.2,0) K2(-6.4,0) K4(-4.8,0) K5(-4,0) K6(-3.2,0) K14(3.2,0) K15(4,0) K16(4.8,0) K18(6.4,0) K19(7.2,0) L1(-7.2,-0.8) L2(-6.4,-0.8) L4(-4.8,-0.8) L5(-4,-0.8) L6(-3.2,-0.8) L14(3.2,-0.8) L15(4,-0.8) L16(4.8,-0.8) L18(6.4,-0.8) L19(7.2,-0.8) M1(-7.2,-1.6) M2(-6.4,-1.6) M4(-4.8,-1.6) M5(-4,-1.6) M6(-3.2,-1.6) M14(3.2,-1.6) M15(4,-1.6) M16(4.8,-1.6) M18(6.4,-1.6) M19(7.2,-1.6) N1(-7.2,-2.4) N2(-6.4,-2.4) N4(-4.8,-2.4) N5(-4,-2.4) N6(-3.2,-2.4) N7(-2.4,-2.4) N13(2.4,-2.4) N14(3.2,-2.4) N15(4,-2.4) N16(4.8,-2.4) N18(6.4,-2.4) N19(7.2,-2.4) P1(-7.2,-3.2) P2(-6.4,-3.2) P4(-4.8,-3.2) P5(-4,-3.2) P6(-3.2,-3.2) P7(-2.4,-3.2) P8(-1.6,-3.2) P9(-0.8,-3.2) P10(0,-3.2) P11(0.8,-3.2) P12(1.6,-3.2) P13(2.4,-3.2) P14(3.2,-3.2) P15(4,-3.2) P16(4.8,-3.2) P18(6.4,-3.2) P19(7.2,-3.2) R1(-7.2,-4) R2(-6.4,-4) R4(-4.8,-4) R5(-4,-4) R6(-3.2,-4) R7(-2.4,-4) R8(-1.6,-4) R9(-0.8,-4) R10(0,-4) R11(0.8,-4) R12(1.6,-4) R13(2.4,-4) R14(3.2,-4) R15(4,-4) R16(4.8,-4) R18(6.4,-4) R19(7.2,-4) T1(-7.2,-4.8) T2(-6.4,-4.8) T4(-4.8,-4.8) T5(-4,-4.8) T6(-3.2,-4.8) T7(-2.4,-4.8) T8(-1.6,-4.8) T9(-0.8,-4.8) T10(0,-4.8) T11(0.8,-4.8) T12(1.6,-4.8) T13(2.4,-4.8) T14(3.2,-4.8) T15(4,-4.8) T16(4.8,-4.8) T18(6.4,-4.8) T19(7.2,-4.8) U1(-7.2,-5.6) U2(-6.4,-5.6) U18(6.4,-5.6) U19(7.2,-5.6) V1(-7.2,-6.4) V2(-6.4,-6.4) V3(-5.6,-6.4) V4(-4.8,-6.4) V5(-4,-6.4) V6(-3.2,-6.4) V7(-2.4,-6.4) V8(-1.6,-6.4) V9(-0.8,-6.4) V10(0,-6.4) V11(0.8,-6.4) V12(1.6,-6.4) V13(2.4,-6.4) V14(3.2,-6.4) V15(4,-6.4) V16(4.8,-6.4) V17(5.6,-6.4) V18(6.4,-6.4) V19(7.2,-6.4) W2(-6.4,-7.2) W3(-5.6,-7.2) W4(-4.8,-7.2) W5(-4,-7.2) W6(-3.2,-7.2) W7(-2.4,-7.2) W8(-1.6,-7.2) W9(-0.8,-7.2) W10(0,-7.2) W11(0.8,-7.2) W12(1.6,-7.2) W13(2.4,-7.2) W14(3.2,-7.2) W15(4,-7.2) W16(4.8,-7.2) W17(5.6,-7.2) W18(6.4,-7.2)
Top Overlay:
  circle w0.25: c-8.66,7.2 r0.125
  lines w0.2: -8,-7 -8,8 7,8 8,7 8,-7 7,-8 -7,-8 -8,-7

## BGA16X16-B280 [mm]
pads (280):
  round 0.45 smd: A1(-7.2,7.2) A2(-6.4,7.2) A3(-5.6,7.2) A4(-4.8,7.2) A5(-4,7.2) A6(-3.2,7.2) A7(-2.4,7.2) A8(-1.6,7.2) A9(-0.8,7.2) A10(0,7.2) A11(0.8,7.2) A12(1.6,7.2) A13(2.4,7.2) A14(3.2,7.2) A15(4,7.2) A16(4.8,7.2) A17(5.6,7.2) A18(6.4,7.2) A19(7.2,7.2) B1(-7.2,6.4) B2(-6.4,6.4) B3(-5.6,6.4) B4(-4.8,6.4) B5(-4,6.4) B6(-3.2,6.4) B7(-2.4,6.4) B8(-1.6,6.4) B9(-0.8,6.4) B10(0,6.4) B11(0.8,6.4) B12(1.6,6.4) B13(2.4,6.4) B14(3.2,6.4) B15(4,6.4) B16(4.8,6.4) B17(5.6,6.4) B18(6.4,6.4) B19(7.2,6.4) C1(-7.2,5.6) C2(-6.4,5.6) C3(-5.6,5.6) C4(-4.8,5.6) C5(-4,5.6) C6(-3.2,5.6) C7(-2.4,5.6) C8(-1.6,5.6) C9(-0.8,5.6) C10(0,5.6) C11(0.8,5.6) C12(1.6,5.6) C13(2.4,5.6) C14(3.2,5.6) C15(4,5.6) C16(4.8,5.6) C17(5.6,5.6) C18(6.4,5.6) C19(7.2,5.6) D1(-7.2,4.8) D2(-6.4,4.8) D3(-5.6,4.8) D4(-4.8,4.8) D5(-4,4.8) D6(-3.2,4.8) D7(-2.4,4.8) D8(-1.6,4.8) D9(-0.8,4.8) D10(0,4.8) D11(0.8,4.8) D12(1.6,4.8) D13(2.4,4.8) D14(3.2,4.8) D15(4,4.8) D16(4.8,4.8) D17(5.6,4.8) D18(6.4,4.8) D19(7.2,4.8) E1(-7.2,4) E2(-6.4,4) E3(-5.6,4) E4(-4.8,4) E5(-4,4) E6(-3.2,4) E7(-2.4,4) E8(-1.6,4) E9(-0.8,4) E10(0,4) E11(0.8,4) E12(1.6,4) E13(2.4,4) E14(3.2,4) E15(4,4) E16(4.8,4) E17(5.6,4) E18(6.4,4) E19(7.2,4) F1(-7.2,3.2) F2(-6.4,3.2) F3(-5.6,3.2) F4(-4.8,3.2) F5(-4,3.2) F15(4,3.2) F16(4.8,3.2) F17(5.6,3.2) F18(6.4,3.2) F19(7.2,3.2) G1(-7.2,2.4) G2(-6.4,2.4) G3(-5.6,2.4) G4(-4.8,2.4) G5(-4,2.4) G15(4,2.4) G16(4.8,2.4) G17(5.6,2.4) G18(6.4,2.4) G19(7.2,2.4) H1(-7.2,1.6) H2(-6.4,1.6) H3(-5.6,1.6) H4(-4.8,1.6) H5(-4,1.6) H15(4,1.6) H16(4.8,1.6) H17(5.6,1.6) H18(6.4,1.6) H19(7.2,1.6) J1(-7.2,0.8) J2(-6.4,0.8) J3(-5.6,0.8) J4(-4.8,0.8) J5(-4,0.8) J15(4,0.8) J16(4.8,0.8) J17(5.6,0.8) J18(6.4,0.8) J19(7.2,0.8) K1(-7.2,0) K2(-6.4,0) K3(-5.6,0) K4(-4.8,0) K5(-4,0) K15(4,0) K16(4.8,0) K17(5.6,0) K18(6.4,0) K19(7.2,0) L1(-7.2,-0.8) L2(-6.4,-0.8) L3(-5.6,-0.8) L4(-4.8,-0.8) L5(-4,-0.8) L15(4,-0.8) L16(4.8,-0.8) L17(5.6,-0.8) L18(6.4,-0.8) L19(7.2,-0.8) M1(-7.2,-1.6) M2(-6.4,-1.6) M3(-5.6,-1.6) M4(-4.8,-1.6) M5(-4,-1.6) M15(4,-1.6) M16(4.8,-1.6) M17(5.6,-1.6) M18(6.4,-1.6) M19(7.2,-1.6) N1(-7.2,-2.4) N2(-6.4,-2.4) N3(-5.6,-2.4) N4(-4.8,-2.4) N5(-4,-2.4) N15(4,-2.4) N16(4.8,-2.4) N17(5.6,-2.4) N18(6.4,-2.4) N19(7.2,-2.4) P1(-7.2,-3.2) P2(-6.4,-3.2) P3(-5.6,-3.2) P4(-4.8,-3.2) P5(-4,-3.2) P15(4,-3.2) P16(4.8,-3.2) P17(5.6,-3.2) P18(6.4,-3.2) P19(7.2,-3.2) R1(-7.2,-4) R2(-6.4,-4) R3(-5.6,-4) R4(-4.8,-4) R5(-4,-4) R6(-3.2,-4) R7(-2.4,-4) R8(-1.6,-4) R9(-0.8,-4) R10(0,-4) R11(0.8,-4) R12(1.6,-4) R13(2.4,-4) R14(3.2,-4) R15(4,-4) R16(4.8,-4) R17(5.6,-4) R18(6.4,-4) R19(7.2,-4) T1(-7.2,-4.8) T2(-6.4,-4.8) T3(-5.6,-4.8) T4(-4.8,-4.8) T5(-4,-4.8) T6(-3.2,-4.8) T7(-2.4,-4.8) T8(-1.6,-4.8) T9(-0.8,-4.8) T10(0,-4.8) T11(0.8,-4.8) T12(1.6,-4.8) T13(2.4,-4.8) T14(3.2,-4.8) T15(4,-4.8) T16(4.8,-4.8) T17(5.6,-4.8) T18(6.4,-4.8) T19(7.2,-4.8) U1(-7.2,-5.6) U2(-6.4,-5.6) U3(-5.6,-5.6) U4(-4.8,-5.6) U5(-4,-5.6) U6(-3.2,-5.6) U7(-2.4,-5.6) U8(-1.6,-5.6) U9(-0.8,-5.6) U10(0,-5.6) U11(0.8,-5.6) U12(1.6,-5.6) U13(2.4,-5.6) U14(3.2,-5.6) U15(4,-5.6) U16(4.8,-5.6) U17(5.6,-5.6) U18(6.4,-5.6) U19(7.2,-5.6) V1(-7.2,-6.4) V2(-6.4,-6.4) V3(-5.6,-6.4) V4(-4.8,-6.4) V5(-4,-6.4) V6(-3.2,-6.4) V7(-2.4,-6.4) V8(-1.6,-6.4) V9(-0.8,-6.4) V10(0,-6.4) V11(0.8,-6.4) V12(1.6,-6.4) V13(2.4,-6.4) V14(3.2,-6.4) V15(4,-6.4) V16(4.8,-6.4) V17(5.6,-6.4) V18(6.4,-6.4) V19(7.2,-6.4) W1(-7.2,-7.2) W2(-6.4,-7.2) W3(-5.6,-7.2) W4(-4.8,-7.2) W5(-4,-7.2) W6(-3.2,-7.2) W7(-2.4,-7.2) W8(-1.6,-7.2) W9(-0.8,-7.2) W10(0,-7.2) W11(0.8,-7.2) W12(1.6,-7.2) W13(2.4,-7.2) W14(3.2,-7.2) W15(4,-7.2) W16(4.8,-7.2) W17(5.6,-7.2) W18(6.4,-7.2) W19(7.2,-7.2)
Top Overlay:
  circle w0.25: c-8.66,7.2 r0.125
  lines w0.2: 7.284,-8 -7.284,-8 -8,-7.284 -8,8 7.284,8 8,7.284 ; 7.284,-8 7.284,-8 ; 7.284,-8 8,-7.284 8,7.284 ; 8,7.284 8,7.284

## BGA16X16-B288 [mm]
pads (288):
  round 0.45 smd: A2(-6.4,7.2) A3(-5.6,7.2) A4(-4.8,7.2) A5(-4,7.2) A6(-3.2,7.2) A7(-2.4,7.2) A8(-1.6,7.2) A9(-0.8,7.2) A10(0,7.2) A11(0.8,7.2) A12(1.6,7.2) A13(2.4,7.2) A14(3.2,7.2) A15(4,7.2) A16(4.8,7.2) A17(5.6,7.2) A18(6.4,7.2) B1(-7.2,6.4) B2(-6.4,6.4) B3(-5.6,6.4) B4(-4.8,6.4) B5(-4,6.4) B6(-3.2,6.4) B7(-2.4,6.4) B8(-1.6,6.4) B9(-0.8,6.4) B10(0,6.4) B11(0.8,6.4) B12(1.6,6.4) B13(2.4,6.4) B14(3.2,6.4) B15(4,6.4) B16(4.8,6.4) B17(5.6,6.4) B18(6.4,6.4) B19(7.2,6.4) C1(-7.2,5.6) C2(-6.4,5.6) C3(-5.6,5.6) C4(-4.8,5.6) C5(-4,5.6) C6(-3.2,5.6) C7(-2.4,5.6) C8(-1.6,5.6) C9(-0.8,5.6) C10(0,5.6) C11(0.8,5.6) C12(1.6,5.6) C13(2.4,5.6) C14(3.2,5.6) C15(4,5.6) C16(4.8,5.6) C17(5.6,5.6) C18(6.4,5.6) C19(7.2,5.6) D1(-7.2,4.8) D2(-6.4,4.8) D3(-5.6,4.8) D17(5.6,4.8) D18(6.4,4.8) D19(7.2,4.8) E1(-7.2,4) E2(-6.4,4) E3(-5.6,4) E5(-4,4) E6(-3.2,4) E7(-2.4,4) E8(-1.6,4) E9(-0.8,4) E10(0,4) E11(0.8,4) E12(1.6,4) E13(2.4,4) E14(3.2,4) E17(5.6,4) E18(6.4,4) E19(7.2,4) F1(-7.2,3.2) F2(-6.4,3.2) F3(-5.6,3.2) F5(-4,3.2) F6(-3.2,3.2) F9(-0.8,3.2) F10(0,3.2) F12(1.6,3.2) F14(3.2,3.2) F15(4,3.2) F17(5.6,3.2) F18(6.4,3.2) F19(7.2,3.2) G1(-7.2,2.4) G2(-6.4,2.4) G3(-5.6,2.4) G5(-4,2.4) G7(-2.4,2.4) G8(-1.6,2.4) G9(-0.8,2.4) G10(0,2.4) G11(0.8,2.4) G12(1.6,2.4) G13(2.4,2.4) G15(4,2.4) G17(5.6,2.4) G18(6.4,2.4) G19(7.2,2.4) H1(-7.2,1.6) H2(-6.4,1.6) H3(-5.6,1.6) H5(-4,1.6) H7(-2.4,1.6) H8(-1.6,1.6) H9(-0.8,1.6) H10(0,1.6) H11(0.8,1.6) H12(1.6,1.6) H13(2.4,1.6) H14(3.2,1.6) H15(4,1.6) H17(5.6,1.6) H18(6.4,1.6) H19(7.2,1.6) J1(-7.2,0.8) J2(-6.4,0.8) J3(-5.6,0.8) J5(-4,0.8) J6(-3.2,0.8) J7(-2.4,0.8) J8(-1.6,0.8) J9(-0.8,0.8) J10(0,0.8) J11(0.8,0.8) J12(1.6,0.8) J13(2.4,0.8) J15(4,0.8) J17(5.6,0.8) J18(6.4,0.8) J19(7.2,0.8) K1(-7.2,0) K2(-6.4,0) K3(-5.6,0) K5(-4,0) K7(-2.4,0) K8(-1.6,0) K9(-0.8,0) K10(0,0) K11(0.8,0) K12(1.6,0) K13(2.4,0) K14(3.2,0) K15(4,0) K17(5.6,0) K18(6.4,0) K19(7.2,0) L1(-7.2,-0.8) L2(-6.4,-0.8) L3(-5.6,-0.8) L5(-4,-0.8) L6(-3.2,-0.8) L7(-2.4,-0.8) L8(-1.6,-0.8) L9(-0.8,-0.8) L10(0,-0.8) L11(0.8,-0.8) L12(1.6,-0.8) L13(2.4,-0.8) L15(4,-0.8) L17(5.6,-0.8) L18(6.4,-0.8) L19(7.2,-0.8) M1(-7.2,-1.6) M2(-6.4,-1.6) M3(-5.6,-1.6) M5(-4,-1.6) M7(-2.4,-1.6) M8(-1.6,-1.6) M9(-0.8,-1.6) M10(0,-1.6) M11(0.8,-1.6) M12(1.6,-1.6) M13(2.4,-1.6) M14(3.2,-1.6) M15(4,-1.6) M17(5.6,-1.6) M18(6.4,-1.6) M19(7.2,-1.6) N1(-7.2,-2.4) N2(-6.4,-2.4) N3(-5.6,-2.4) N5(-4,-2.4) N7(-2.4,-2.4) N8(-1.6,-2.4) N9(-0.8,-2.4) N10(0,-2.4) N11(0.8,-2.4) N12(1.6,-2.4) N13(2.4,-2.4) N15(4,-2.4) N17(5.6,-2.4) N18(6.4,-2.4) N19(7.2,-2.4) P1(-7.2,-3.2) P2(-6.4,-3.2) P3(-5.6,-3.2) P5(-4,-3.2) P6(-3.2,-3.2) P9(-0.8,-3.2) P12(1.6,-3.2) P14(3.2,-3.2) P15(4,-3.2) P17(5.6,-3.2) P18(6.4,-3.2) P19(7.2,-3.2) R1(-7.2,-4) R2(-6.4,-4) R3(-5.6,-4) R6(-3.2,-4) R7(-2.4,-4) R8(-1.6,-4) R9(-0.8,-4) R10(0,-4) R11(0.8,-4) R12(1.6,-4) R13(2.4,-4) R14(3.2,-4) R17(5.6,-4) R18(6.4,-4) R19(7.2,-4) T1(-7.2,-4.8) T2(-6.4,-4.8) T3(-5.6,-4.8) T17(5.6,-4.8) T18(6.4,-4.8) T19(7.2,-4.8) U1(-7.2,-5.6) U2(-6.4,-5.6) U3(-5.6,-5.6) U4(-4.8,-5.6) U5(-4,-5.6) U6(-3.2,-5.6) U7(-2.4,-5.6) U8(-1.6,-5.6) U9(-0.8,-5.6) U10(0,-5.6) U11(0.8,-5.6) U12(1.6,-5.6) U13(2.4,-5.6) U14(3.2,-5.6) U15(4,-5.6) U16(4.8,-5.6) U17(5.6,-5.6) U18(6.4,-5.6) U19(7.2,-5.6) V1(-7.2,-6.4) V2(-6.4,-6.4) V3(-5.6,-6.4) V4(-4.8,-6.4) V5(-4,-6.4) V6(-3.2,-6.4) V7(-2.4,-6.4) V8(-1.6,-6.4) V9(-0.8,-6.4) V10(0,-6.4) V11(0.8,-6.4) V12(1.6,-6.4) V13(2.4,-6.4) V14(3.2,-6.4) V15(4,-6.4) V16(4.8,-6.4) V17(5.6,-6.4) V18(6.4,-6.4) V19(7.2,-6.4) W2(-6.4,-7.2) W3(-5.6,-7.2) W4(-4.8,-7.2) W5(-4,-7.2) W6(-3.2,-7.2) W7(-2.4,-7.2) W8(-1.6,-7.2) W9(-0.8,-7.2) W10(0,-7.2) W11(0.8,-7.2) W12(1.6,-7.2) W13(2.4,-7.2) W14(3.2,-7.2) W15(4,-7.2) W16(4.8,-7.2) W17(5.6,-7.2) W18(6.4,-7.2)
Top Overlay:
  circle w0.25: c-8.66,7.2 r0.125
  lines w0.2: -8,-7 -8,8 7,8 8,7 8,-7 7,-8 -7,-8 -8,-7

## BGA17x17-B332 [mm]
pads (361):
  round 0.45 smd: A1(-7.2,7.2) A2(-6.4,7.2) A3(-5.6,7.2) A4(-4.8,7.2) A5(-4,7.2) A6(-3.2,7.2) A7(-2.4,7.2) A8(-1.6,7.2) A9(-0.8,7.2) A10(0,7.2) A11(0.8,7.2) A12(1.6,7.2) A13(2.4,7.2) A14(3.2,7.2) A15(4,7.2) A16(4.8,7.2) A17(5.6,7.2) A18(6.4,7.2) A19(7.2,7.2) B1(-7.2,6.4) B2(-6.4,6.4) B3(-5.6,6.4) B4(-4.8,6.4) B5(-4,6.4) B6(-3.2,6.4) B7(-2.4,6.4) B8(-1.6,6.4) B9(-0.8,6.4) B10(0,6.4) B11(0.8,6.4) B12(1.6,6.4) B13(2.4,6.4) B14(3.2,6.4) B15(4,6.4) B16(4.8,6.4) B17(5.6,6.4) B18(6.4,6.4) B19(7.2,6.4) C1(-7.2,5.6) C2(-6.4,5.6) C3(-5.6,5.6) C4(-4.8,5.6) C5(-4,5.6) C6(-3.2,5.6) C7(-2.4,5.6) C8(-1.6,5.6) C9(-0.8,5.6) C10(0,5.6) C11(0.8,5.6) C12(1.6,5.6) C13(2.4,5.6) C14(3.2,5.6) C15(4,5.6) C16(4.8,5.6) C17(5.6,5.6) C18(6.4,5.6) C19(7.2,5.6) D1(-7.2,4.8) D2(-6.4,4.8) D3(-5.6,4.8) D4(-4.8,4.8) D5(-4,4.8) D6(-3.2,4.8) D7(-2.4,4.8) D8(-1.6,4.8) D9(-0.8,4.8) D10(0,4.8) D11(0.8,4.8) D12(1.6,4.8) D13(2.4,4.8) D14(3.2,4.8) D15(4,4.8) D16(4.8,4.8) D17(5.6,4.8) D18(6.4,4.8) D19(7.2,4.8) E1(-7.2,4) E2(-6.4,4) E3(-5.6,4) E4(-4.8,4) E5(-4,4) E6(-3.2,4) E7(-2.4,4) E8(-1.6,4) E9(-0.8,4) E10(0,4) E11(0.8,4) E12(1.6,4) E13(2.4,4) E14(3.2,4) E15(4,4) E16(4.8,4) E17(5.6,4) E18(6.4,4) E19(7.2,4) F1(-7.2,3.2) F2(-6.4,3.2) F3(-5.6,3.2) F4(-4.8,3.2) F5(-4,3.2) F6(-3.2,3.2) F7(-2.4,3.2) F8(-1.6,3.2) F9(-0.8,3.2) F10(0,3.2) F11(0.8,3.2) F12(1.6,3.2) F13(2.4,3.2) F14(3.2,3.2) F15(4,3.2) F16(4.8,3.2) F17(5.6,3.2) F18(6.4,3.2) F19(7.2,3.2) G1(-7.2,2.4) G2(-6.4,2.4) G3(-5.6,2.4) G4(-4.8,2.4) G5(-4,2.4) G6(-3.2,2.4) G7(-2.4,2.4) G8(-1.6,2.4) G9(-0.8,2.4) G10(0,2.4) G11(0.8,2.4) G12(1.6,2.4) G13(2.4,2.4) G14(3.2,2.4) G15(4,2.4) G16(4.8,2.4) G17(5.6,2.4) G18(6.4,2.4) G19(7.2,2.4) H1(-7.2,1.6) H2(-6.4,1.6) H3(-5.6,1.6) H4(-4.8,1.6) H5(-4,1.6) H6(-3.2,1.6) H7(-2.4,1.6) H8(-1.6,1.6) H9(-0.8,1.6) H10(0,1.6) H11(0.8,1.6) H12(1.6,1.6) H13(2.4,1.6) H14(3.2,1.6) H15(4,1.6) H16(4.8,1.6) H17(5.6,1.6) H18(6.4,1.6) H19(7.2,1.6) J1(-7.2,0.8) J2(-6.4,0.8) J3(-5.6,0.8) J4(-4.8,0.8) J5(-4,0.8) J6(-3.2,0.8) J7(-2.4,0.8) J8(-1.6,0.8) J9(-0.8,0.8) J10(0,0.8) J11(0.8,0.8) J12(1.6,0.8) J13(2.4,0.8) J14(3.2,0.8) J15(4,0.8) J16(4.8,0.8) J17(5.6,0.8) J18(6.4,0.8) J19(7.2,0.8) K1(-7.2,0) K2(-6.4,0) K3(-5.6,0) K4(-4.8,0) K5(-4,0) K6(-3.2,0) K7(-2.4,0) K8(-1.6,0) K9(-0.8,0) K10(0,0) K11(0.8,0) K12(1.6,0) K13(2.4,0) K14(3.2,0) K15(4,0) K16(4.8,0) K17(5.6,0) K18(6.4,0) K19(7.2,0) L1(-7.2,-0.8) L2(-6.4,-0.8) L3(-5.6,-0.8) L4(-4.8,-0.8) L5(-4,-0.8) L6(-3.2,-0.8) L7(-2.4,-0.8) L8(-1.6,-0.8) L9(-0.8,-0.8) L10(0,-0.8) L11(0.8,-0.8) L12(1.6,-0.8) L13(2.4,-0.8) L14(3.2,-0.8) L15(4,-0.8) L16(4.8,-0.8) L17(5.6,-0.8) L18(6.4,-0.8) L19(7.2,-0.8) M1(-7.2,-1.6) M2(-6.4,-1.6) M3(-5.6,-1.6) M4(-4.8,-1.6) M5(-4,-1.6) M6(-3.2,-1.6) M7(-2.4,-1.6) M8(-1.6,-1.6) M9(-0.8,-1.6) M10(0,-1.6) M11(0.8,-1.6) M12(1.6,-1.6) M13(2.4,-1.6) M14(3.2,-1.6) M15(4,-1.6) M16(4.8,-1.6) M17(5.6,-1.6) M18(6.4,-1.6) M19(7.2,-1.6) N1(-7.2,-2.4) N2(-6.4,-2.4) N3(-5.6,-2.4) N4(-4.8,-2.4) N5(-4,-2.4) N6(-3.2,-2.4) N7(-2.4,-2.4) N8(-1.6,-2.4) N9(-0.8,-2.4) N10(0,-2.4) N11(0.8,-2.4) N12(1.6,-2.4) N13(2.4,-2.4) N14(3.2,-2.4) N15(4,-2.4) N16(4.8,-2.4) N17(5.6,-2.4) N18(6.4,-2.4) N19(7.2,-2.4) P1(-7.2,-3.2) P2(-6.4,-3.2) P3(-5.6,-3.2) P4(-4.8,-3.2) P5(-4,-3.2) P6(-3.2,-3.2) P7(-2.4,-3.2) P8(-1.6,-3.2) P9(-0.8,-3.2) P10(0,-3.2) P11(0.8,-3.2) P12(1.6,-3.2) P13(2.4,-3.2) P14(3.2,-3.2) P15(4,-3.2) P16(4.8,-3.2) P17(5.6,-3.2) P18(6.4,-3.2) P19(7.2,-3.2) R1(-7.2,-4) R2(-6.4,-4) R3(-5.6,-4) R4(-4.8,-4) R5(-4,-4) R6(-3.2,-4) R7(-2.4,-4) R8(-1.6,-4) R9(-0.8,-4) R10(0,-4) R11(0.8,-4) R12(1.6,-4) R13(2.4,-4) R14(3.2,-4) R15(4,-4) R16(4.8,-4) R17(5.6,-4) R18(6.4,-4) R19(7.2,-4) T1(-7.2,-4.8) T2(-6.4,-4.8) T3(-5.6,-4.8) T4(-4.8,-4.8) T5(-4,-4.8) T6(-3.2,-4.8) T7(-2.4,-4.8) T8(-1.6,-4.8) T9(-0.8,-4.8) T10(0,-4.8) T11(0.8,-4.8) T12(1.6,-4.8) T13(2.4,-4.8) T14(3.2,-4.8) T15(4,-4.8) T16(4.8,-4.8) T17(5.6,-4.8) T18(6.4,-4.8) T19(7.2,-4.8) U1(-7.2,-5.6) U2(-6.4,-5.6) U3(-5.6,-5.6) U4(-4.8,-5.6) U5(-4,-5.6) U6(-3.2,-5.6) U7(-2.4,-5.6) U8(-1.6,-5.6) U9(-0.8,-5.6) U10(0,-5.6) U11(0.8,-5.6) U12(1.6,-5.6) U13(2.4,-5.6) U14(3.2,-5.6) U15(4,-5.6) U16(4.8,-5.6) U17(5.6,-5.6) U18(6.4,-5.6) U19(7.2,-5.6) V1(-7.2,-6.4) V2(-6.4,-6.4) V3(-5.6,-6.4) V4(-4.8,-6.4) V5(-4,-6.4) V6(-3.2,-6.4) V7(-2.4,-6.4) V8(-1.6,-6.4) V9(-0.8,-6.4) V10(0,-6.4) V11(0.8,-6.4) V12(1.6,-6.4) V13(2.4,-6.4) V14(3.2,-6.4) V15(4,-6.4) V16(4.8,-6.4) V17(5.6,-6.4) V18(6.4,-6.4) V19(7.2,-6.4) W1(-7.2,-7.2) W2(-6.4,-7.2) W3(-5.6,-7.2) W4(-4.8,-7.2) W5(-4,-7.2) W6(-3.2,-7.2) W7(-2.4,-7.2) W8(-1.6,-7.2) W9(-0.8,-7.2) W10(0,-7.2) W11(0.8,-7.2) W12(1.6,-7.2) W13(2.4,-7.2) W14(3.2,-7.2) W15(4,-7.2) W16(4.8,-7.2) W17(5.6,-7.2) W18(6.4,-7.2) W19(7.2,-7.2)
Top Overlay:
  circle w0.25: c-9.155,7.2 r0.125
  lines w0.2: -8.5,-7.5 -7.5,-8.5 7.5,-8.5 8.5,-7.5 8.5,7.5 7.5,8.5 -8.5,8.5 -8.5,-7.5

## BGA18X18-B340 [mm]
pads (340):
  round 0.45 smd: A1(-8.4,8.4) A2(-7.6,8.4) A3(-6.8,8.4) A4(-6,8.4) A5(-5.2,8.4) A6(-4.4,8.4) A7(-3.6,8.4) A8(-2.8,8.4) A9(-2,8.4) A10(-1.2,8.4) A11(-0.4,8.4) A12(0.4,8.4) A13(1.2,8.4) A14(2,8.4) A15(2.8,8.4) A16(3.6,8.4) A17(4.4,8.4) A18(5.2,8.4) A19(6,8.4) A20(6.8,8.4) A21(7.6,8.4) A22(8.4,8.4) AA1(-8.4,-7.6) AA2(-7.6,-7.6) AA3(-6.8,-7.6) AA4(-6,-7.6) AA5(-5.2,-7.6) AA6(-4.4,-7.6) AA7(-3.6,-7.6) AA8(-2.8,-7.6) AA9(-2,-7.6) AA10(-1.2,-7.6) AA11(-0.4,-7.6) AA12(0.4,-7.6) AA13(1.2,-7.6) AA14(2,-7.6) AA15(2.8,-7.6) AA16(3.6,-7.6) AA17(4.4,-7.6) AA18(5.2,-7.6) AA19(6,-7.6) AA20(6.8,-7.6) AA21(7.6,-7.6) AA22(8.4,-7.6) AB1(-8.4,-8.4) AB2(-7.6,-8.4) AB3(-6.8,-8.4) AB4(-6,-8.4) AB5(-5.2,-8.4) AB6(-4.4,-8.4) AB7(-3.6,-8.4) AB8(-2.8,-8.4) AB9(-2,-8.4) AB10(-1.2,-8.4) AB11(-0.4,-8.4) AB12(0.4,-8.4) AB13(1.2,-8.4) AB14(2,-8.4) AB15(2.8,-8.4) AB16(3.6,-8.4) AB17(4.4,-8.4) AB18(5.2,-8.4) AB19(6,-8.4) AB20(6.8,-8.4) AB21(7.6,-8.4) AB22(8.4,-8.4) B1(-8.4,7.6) B2(-7.6,7.6) B3(-6.8,7.6) B4(-6,7.6) B5(-5.2,7.6) B6(-4.4,7.6) B7(-3.6,7.6) B8(-2.8,7.6) B9(-2,7.6) B10(-1.2,7.6) B11(-0.4,7.6) B12(0.4,7.6) B13(1.2,7.6) B14(2,7.6) B15(2.8,7.6) B16(3.6,7.6) B17(4.4,7.6) B18(5.2,7.6) B19(6,7.6) B20(6.8,7.6) B21(7.6,7.6) B22(8.4,7.6) C1(-8.4,6.8) C2(-7.6,6.8) C3(-6.8,6.8) C4(-6,6.8) C5(-5.2,6.8) C6(-4.4,6.8) C7(-3.6,6.8) C8(-2.8,6.8) C9(-2,6.8) C10(-1.2,6.8) C11(-0.4,6.8) C12(0.4,6.8) C13(1.2,6.8) C14(2,6.8) C15(2.8,6.8) C16(3.6,6.8) C17(4.4,6.8) C18(5.2,6.8) C19(6,6.8) C20(6.8,6.8) C21(7.6,6.8) C22(8.4,6.8) D1(-8.4,6) D2(-7.6,6) D3(-6.8,6) D4(-6,6) D5(-5.2,6) D6(-4.4,6) D7(-3.6,6) D8(-2.8,6) D9(-2,6) D10(-1.2,6) D11(-0.4,6) D12(0.4,6) D13(1.2,6) D14(2,6) D15(2.8,6) D16(3.6,6) D17(4.4,6) D18(5.2,6) D19(6,6) D20(6.8,6) D21(7.6,6) D22(8.4,6) E1(-8.4,5.2) E2(-7.6,5.2) E3(-6.8,5.2) E4(-6,5.2) E5(-5.2,5.2) E6(-4.4,5.2) E7(-3.6,5.2) E8(-2.8,5.2) E9(-2,5.2) E10(-1.2,5.2) E11(-0.4,5.2) E12(0.4,5.2) E13(1.2,5.2) E14(2,5.2) E15(2.8,5.2) E16(3.6,5.2) E17(4.4,5.2) E18(5.2,5.2) E19(6,5.2) E20(6.8,5.2) E21(7.6,5.2) E22(8.4,5.2) F1(-8.4,4.4) F2(-7.6,4.4) F3(-6.8,4.4) F4(-6,4.4) F5(-5.2,4.4) F18(5.2,4.4) F19(6,4.4) F20(6.8,4.4) F21(7.6,4.4) F22(8.4,4.4) G1(-8.4,3.6) G2(-7.6,3.6) G3(-6.8,3.6) G4(-6,3.6) G5(-5.2,3.6) G18(5.2,3.6) G19(6,3.6) G20(6.8,3.6) G21(7.6,3.6) G22(8.4,3.6) H1(-8.4,2.8) H2(-7.6,2.8) H3(-6.8,2.8) H4(-6,2.8) H5(-5.2,2.8) H18(5.2,2.8) H19(6,2.8) H20(6.8,2.8) H21(7.6,2.8) H22(8.4,2.8) J1(-8.4,2) J2(-7.6,2) J3(-6.8,2) J4(-6,2) J5(-5.2,2) J18(5.2,2) J19(6,2) J20(6.8,2) J21(7.6,2) J22(8.4,2) K1(-8.4,1.2) K2(-7.6,1.2) K3(-6.8,1.2) K4(-6,1.2) K5(-5.2,1.2) K18(5.2,1.2) K19(6,1.2) K20(6.8,1.2) K21(7.6,1.2) K22(8.4,1.2) L1(-8.4,0.4) L2(-7.6,0.4) L3(-6.8,0.4) L4(-6,0.4) L5(-5.2,0.4) L18(5.2,0.4) L19(6,0.4) L20(6.8,0.4) L21(7.6,0.4) L22(8.4,0.4) M1(-8.4,-0.4) M2(-7.6,-0.4) M3(-6.8,-0.4) M4(-6,-0.4) M5(-5.2,-0.4) M18(5.2,-0.4) M19(6,-0.4) M20(6.8,-0.4) M21(7.6,-0.4) M22(8.4,-0.4) N1(-8.4,-1.2) N2(-7.6,-1.2) N3(-6.8,-1.2) N4(-6,-1.2) N5(-5.2,-1.2) N18(5.2,-1.2) N19(6,-1.2) N20(6.8,-1.2) N21(7.6,-1.2) N22(8.4,-1.2) P1(-8.4,-2) P2(-7.6,-2) P3(-6.8,-2) P4(-6,-2) P5(-5.2,-2) P18(5.2,-2) P19(6,-2) P20(6.8,-2) P21(7.6,-2) P22(8.4,-2) R1(-8.4,-2.8) R2(-7.6,-2.8) R3(-6.8,-2.8) R4(-6,-2.8) R5(-5.2,-2.8) R18(5.2,-2.8) R19(6,-2.8) R20(6.8,-2.8) R21(7.6,-2.8) R22(8.4,-2.8) T1(-8.4,-3.6) T2(-7.6,-3.6) T3(-6.8,-3.6) T4(-6,-3.6) T5(-5.2,-3.6) T18(5.2,-3.6) T19(6,-3.6) T20(6.8,-3.6) T21(7.6,-3.6) T22(8.4,-3.6) U1(-8.4,-4.4) U2(-7.6,-4.4) U3(-6.8,-4.4) U4(-6,-4.4) U5(-5.2,-4.4) U18(5.2,-4.4) U19(6,-4.4) U20(6.8,-4.4) U21(7.6,-4.4) U22(8.4,-4.4) V1(-8.4,-5.2) V2(-7.6,-5.2) V3(-6.8,-5.2) V4(-6,-5.2) V5(-5.2,-5.2) V6(-4.4,-5.2) V7(-3.6,-5.2) V8(-2.8,-5.2) V9(-2,-5.2) V10(-1.2,-5.2) V11(-0.4,-5.2) V12(0.4,-5.2) V13(1.2,-5.2) V14(2,-5.2) V15(2.8,-5.2) V16(3.6,-5.2) V17(4.4,-5.2) V18(5.2,-5.2) V19(6,-5.2) V20(6.8,-5.2) V21(7.6,-5.2) V22(8.4,-5.2) W1(-8.4,-6) W2(-7.6,-6) W3(-6.8,-6) W4(-6,-6) W5(-5.2,-6) W6(-4.4,-6) W7(-3.6,-6) W8(-2.8,-6) W9(-2,-6) W10(-1.2,-6) W11(-0.4,-6) W12(0.4,-6) W13(1.2,-6) W14(2,-6) W15(2.8,-6) W16(3.6,-6) W17(4.4,-6) W18(5.2,-6) W19(6,-6) W20(6.8,-6) W21(7.6,-6) W22(8.4,-6) Y1(-8.4,-6.8) Y2(-7.6,-6.8) Y3(-6.8,-6.8) Y4(-6,-6.8) Y5(-5.2,-6.8) Y6(-4.4,-6.8) Y7(-3.6,-6.8) Y8(-2.8,-6.8) Y9(-2,-6.8) Y10(-1.2,-6.8) Y11(-0.4,-6.8) Y12(0.4,-6.8) Y13(1.2,-6.8) Y14(2,-6.8) Y15(2.8,-6.8) Y16(3.6,-6.8) Y17(4.4,-6.8) Y18(5.2,-6.8) Y19(6,-6.8) Y20(6.8,-6.8) Y21(7.6,-6.8) Y22(8.4,-6.8)
Top Overlay:
  circle w0.25: c-9.76,8.4 r0.125
  lines w0.2: -9.1,-8.584 -9.1,9.1 8.584,9.1 9.1,8.584 9.1,-8.584 8.584,-9.1 -8.584,-9.1 -9.1,-8.584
